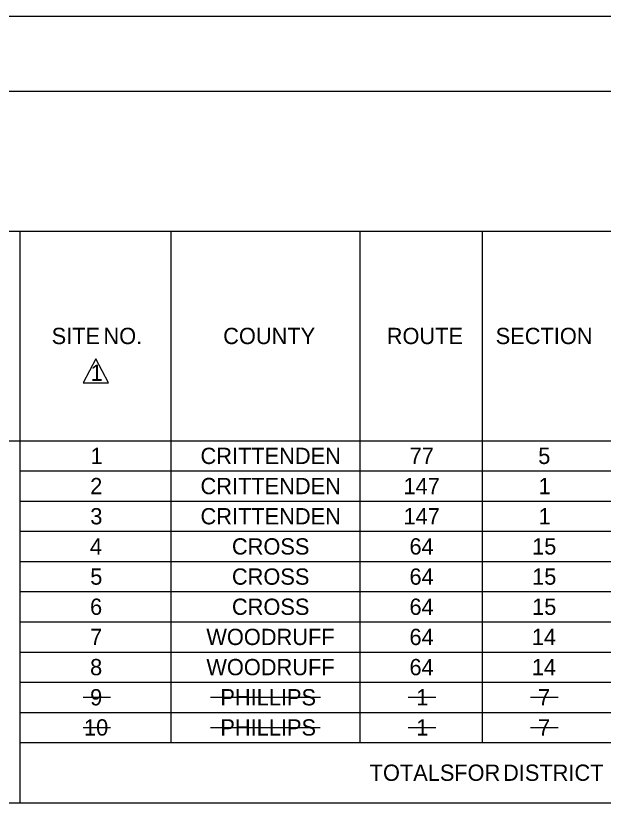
# Model space of a CAD drawing. Extents: x 18 to 14744716, y -5 to 1829144.
# Drawn here: x 20.27 to 24.77, y 10.48 to 16.63 of the extents above; entities that cross this region are included whole.
import ezdxf

# ---------------------------------------------------------------- set-up
doc = ezdxf.new("R2010")
doc.units = 0
for name, color, linetype in [('B_Dimensions', 7, 'Continuous'), ('B_Text', 7, 'Continuous'), ('R_Border', 7, 'Continuous'), ('R_No Plot', 7, 'Continuous')]:
    doc.layers.add(name, color=color, linetype=linetype)

msp = doc.modelspace()

# ---------------------------------------------------------------- linework, layer by layer
at = {"layer": 'B_Dimensions'}
for p, q in [((20.8822, 14.0018), (20.7857, 13.8179)), ((20.9787, 13.8179), (20.8822, 14.0018)), ((20.7857, 13.8179), (20.9787, 13.8179)), ((20.7857, 11.4082), (20.9962, 11.4082)), ((21.7602, 11.4082), (22.6042, 11.4082)), ((23.2759, 11.4082), (23.4864, 11.4082)), ((24.2129, 11.4082), (24.4234, 11.4082)), ((20.7857, 11.177), (20.9962, 11.177)), ((21.7602, 11.177), (22.6004, 11.177)), ((23.2759, 11.177), (23.4864, 11.177)), ((24.2129, 11.177), (24.4234, 11.177))]:
    msp.add_line(p, q, dxfattribs=at)
at = {"layer": 'B_Text'}
for p, q in [((19.3916, 14.9795), (51.1014, 14.9795)), ((20.3042, 10.599), (20.3042, 14.9795)), ((21.4602, 11.0614), (21.4602, 14.9795)), ((22.9082, 11.0614), (22.9082, 14.9795)), ((23.8451, 11.0614), (23.8451, 14.9795)), ((19.3916, 13.3733), (51.1014, 13.3733)), ((20.3042, 10.599), (20.3042, 13.3733)), ((20.3042, 13.1421), (51.1014, 13.1421)), ((20.3042, 12.9109), (51.1014, 12.9109)), ((20.3042, 12.6797), (51.1014, 12.6797)), ((20.3042, 12.4485), (51.1014, 12.4485)), ((20.3042, 12.2173), (51.1014, 12.2173)), ((20.3042, 11.9861), (51.1014, 11.9861)), ((20.3042, 11.7549), (51.1014, 11.7549)), ((20.3042, 11.5238), (51.1014, 11.5238)), ((20.3042, 11.2926), (51.1014, 11.2926)), ((20.3042, 11.0614), (51.1014, 11.0614)), ((19.3916, 10.599), (51.1014, 10.599))]:
    msp.add_line(p, q, dxfattribs=at)
at = {"layer": 'R_Border'}
msp.add_line((19.2929, 16.0508), (51.2001, 16.0508), dxfattribs=at)
at = {"layer": 'R_No Plot'}
msp.add_lwpolyline([(17.7769, 16.6276), (51.7769, 16.6276), (51.7769, -5.3724), (17.7769, -5.3724)], close=True, dxfattribs=at)

# ---------------------------------------------------------------- texts
at = {"layer": 'B_Text'}
for s, p in [('SITE', (20.5442, 14.114)), (' NO.', (20.8947, 14.114)), ('COUNTY', (21.8582, 14.114)), ('ROUTE', (23.1109, 14.114)), ('SECTION', (23.9455, 14.114)), ('1', (20.8423, 13.8324)), ('1', (20.8423, 13.1953)), ('CRITTENDEN', (21.6844, 13.1953)), ('77', (23.2861, 13.1953)), ('5', (24.2712, 13.1953)), ('2', (20.8392, 12.9641)), ('CRITTENDEN', (21.6844, 12.9641)), ('147', (23.2392, 12.9641)), ('1', (24.2737, 12.9641)), ('3', (20.8402, 12.7329)), ('CRITTENDEN', (21.6844, 12.7329)), ('147', (23.2392, 12.7329)), ('1', (24.2737, 12.7329)), ('4', (20.8375, 12.5017)), ('CROSS', (21.9252, 12.5017)), ('64', (23.2851, 12.5017)), ('15', (24.2244, 12.5017)), ('5', (20.8398, 12.2705)), ('CROSS', (21.9252, 12.2705)), ('64', (23.2851, 12.2705)), ('15', (24.2244, 12.2705)), ('6', (20.8382, 12.0393)), ('CROSS', (21.9252, 12.0393)), ('64', (23.2851, 12.0393)), ('15', (24.2244, 12.0393)), ('7', (20.8385, 11.8081)), ('WOODRUFF', (21.7292, 11.8081)), ('64', (23.2851, 11.8081)), ('14', (24.222, 11.8081)), ('8', (20.8385, 11.5769)), ('WOODRUFF', (21.7292, 11.5769)), ('64', (23.2851, 11.5769)), ('14', (24.222, 11.5769)), ('9', (20.8389, 11.3458)), ('PHILLIPS', (21.8365, 11.3458)), ('1', (23.3367, 11.3458)), ('7', (24.2698, 11.3458)), ('10', (20.792, 11.1146)), ('PHILLIPS', (21.8365, 11.1146)), ('1', (23.3367, 11.1146)), ('7', (24.2698, 11.1146)), ('TOTALS', (22.9802, 10.7678)), (' FOR', (23.5817, 10.7678)), (' DISTRICT', (23.9555, 10.7678))]:
    msp.add_text(s, height=0.1248, dxfattribs=at).set_placement(p)

doc.saveas('drawing.dxf')
